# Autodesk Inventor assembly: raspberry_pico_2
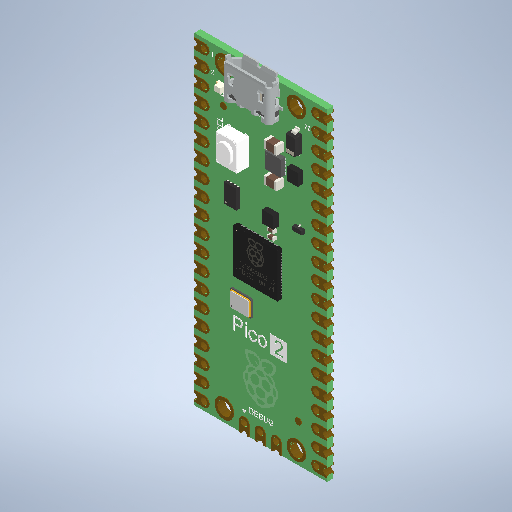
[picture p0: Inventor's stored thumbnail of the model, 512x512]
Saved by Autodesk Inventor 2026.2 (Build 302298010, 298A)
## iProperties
Created: 2026-06
Part Number: raspberry_pico_2
Description: FreeCAD Model
Document SubType Name: Assembly
Designer: mel
Authority: Unknown
Title: Open CASCADE Shape Model
Sending System: FreeCAD
Preprocessor: Open CASCADE STEP processor 7.8
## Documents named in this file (10)
- D:\travail\année 2026-2027\1 sti2d IT\poubelle à verre\raspberry-pico-2-microcontroller-rp2350-1.snapshot.5\raspberry_pico_2\raspberry_pico_2\raspberry_pico_2.iam
- D:\travail\année 2026-2027\1 sti2d IT\poubelle à verre\raspberry-pico-2-microcontroller-rp2350-1.snapshot.5\raspberry_pico_2\raspberry_pico_2\Groupe_pcb.iam
- D:\travail\année 2026-2027\1 sti2d IT\poubelle à verre\raspberry-pico-2-microcontroller-rp2350-1.snapshot.5\raspberry_pico_2\raspberry_pico_2\micro_usb_connector v17 v1.iam
- D:\travail\année 2026-2027\1 sti2d IT\poubelle à verre\raspberry-pico-2-microcontroller-rp2350-1.snapshot.5\raspberry_pico_2\raspberry_pico_2\LFXTAL055299Reel008.iam
- D:\travail\année 2026-2027\1 sti2d IT\poubelle à verre\raspberry-pico-2-microcontroller-rp2350-1.snapshot.5\raspberry_pico_2\raspberry_pico_2\tactile_switch.ipt
- D:\travail\année 2026-2027\1 sti2d IT\poubelle à verre\raspberry-pico-2-microcontroller-rp2350-1.snapshot.5\raspberry_pico_2\raspberry_pico_2\silkscreen_recto.iam
- D:\travail\année 2026-2027\1 sti2d IT\poubelle à verre\raspberry-pico-2-microcontroller-rp2350-1.snapshot.5\raspberry_pico_2\raspberry_pico_2\Components_recto.iam
- D:\travail\année 2026-2027\1 sti2d IT\poubelle à verre\raspberry-pico-2-microcontroller-rp2350-1.snapshot.5\raspberry_pico_2\raspberry_pico_2\TP_verso.iam
- D:\travail\année 2026-2027\1 sti2d IT\poubelle à verre\raspberry-pico-2-microcontroller-rp2350-1.snapshot.5\raspberry_pico_2\raspberry_pico_2\Silkscreen_bottom-p1.iam
- D:\travail\année 2026-2027\1 sti2d IT\poubelle à verre\raspberry-pico-2-microcontroller-rp2350-1.snapshot.5\raspberry_pico_2\raspberry_pico_2\Silkscreen_bottom_p2.iam
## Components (9 placed, 9 different names)
1. 2632 [sub-assembly]
2. 2641 [sub-assembly]
3. 2650 [sub-assembly]
4. 2651
5. 2663 [sub-assembly]
6. 2782 [sub-assembly]
7. 2790 [sub-assembly]
8. 2813 [sub-assembly]
9. 2845 [sub-assembly]
